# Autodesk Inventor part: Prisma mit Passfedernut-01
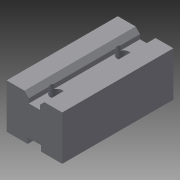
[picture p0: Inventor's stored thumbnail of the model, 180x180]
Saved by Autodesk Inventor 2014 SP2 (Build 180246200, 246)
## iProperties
Created: 2015-06
Part Number: Prisma mit Passfedernut-01
Material: Generisch
Document SubType Name: Modeling
Designer: e_krauts
Density: 1 g/cm^3
Appearance: Vorgabe
Mass: 22.6626 g
Surface Area: 62.7393 cm^2
Volume: 22.6626 cm^3
Author: e_krauts
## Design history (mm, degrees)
derived "Prisma mit Passfedernut.ipt"
feature "Volumenkörper1::Prisma mit Passfedernut.ipt"
tag "Bezeichnung1"
node "Volumenkörper1"
other parameters: "d7" = 5, "d8" = 4, "d9" = 2, "d10" = 45 deg, "d11" = 25, "d14" = 0, "d17" = 6, "d18" = 2.5, "d20" = 0, "d22" = 2.9, "d24" = 5.5, "d29" = 8, "d30" = 2.25, "d32" = 0, "d33" = 2.9, "d35" = 5.5
